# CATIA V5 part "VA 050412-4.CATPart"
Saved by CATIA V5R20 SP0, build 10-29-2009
Part number: VA 050412-4
Revision: ANY
Definition: UNKNOWN
Nomenclature: VA 050412-4
Source: Unknown
Bounding box of the stored display mesh (mm): x -1.25 to 1.25, y 0 to 2, z -1.393 to 1.393
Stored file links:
  C:\Users\Utente\Desktop\IO LAVORO\3D X SITO CF\CUMSA\3D files VA\VA 050412\VA 050412-4.CATPart
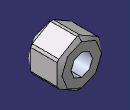
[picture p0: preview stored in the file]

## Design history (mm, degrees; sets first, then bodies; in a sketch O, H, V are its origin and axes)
Body1 "Cortar-Revolución1" (main body)
  Solid1: solid without history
